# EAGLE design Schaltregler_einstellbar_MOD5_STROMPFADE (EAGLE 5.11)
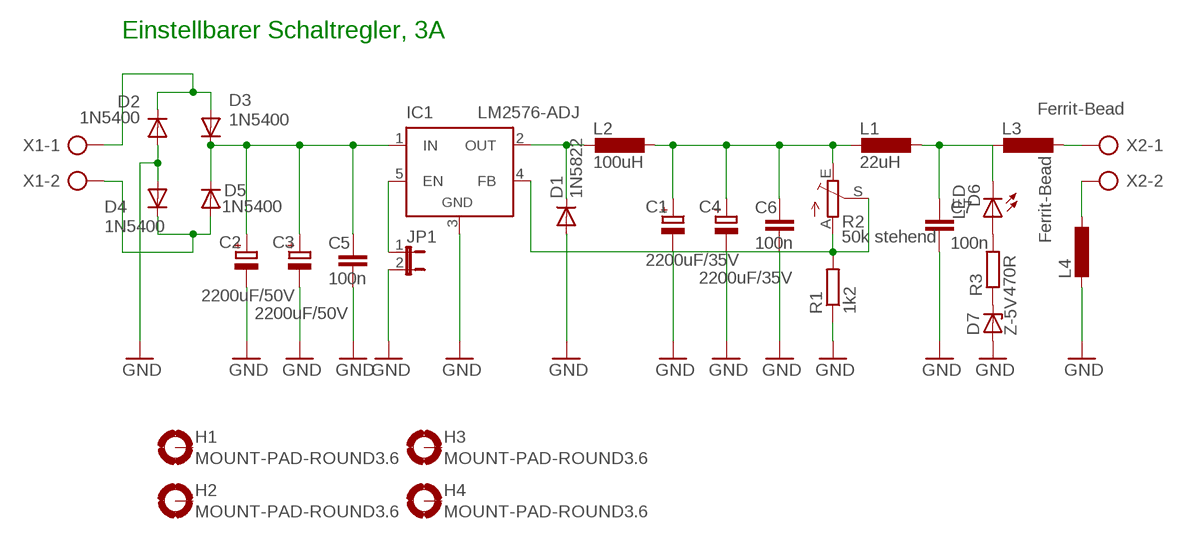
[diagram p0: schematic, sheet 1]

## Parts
C1  2200uF/35V  CPOL-EUE5-13  [E5-13]
C2  2200uF/50V  CPOL-EUE7.5-16  [E7,5-16]
C3  2200uF/50V  CPOL-EUE7.5-16  [E7,5-16]
C4  2200uF/35V  CPOL-EUE5-13  [E5-13]
C5  100n  C-EU025-024X044  [C025-024X044]
C6  100n  C-EU025-024X044  [C025-024X044]
C7  100n  C-EU025-024X044  [C025-024X044]
D1  1N5822  BYW80  [TO220ACS]
D2  1N5400  [DO201-15]
D3  1N5400  [DO201-15]
D4  1N5400  [DO201-15]
D5  1N5400  [DO201-15]
D6  LED  LED5MM  [LED5MM]
D7  Z-5V  ZENER-DIODEF126-10  [F126Z10]
H1  MOUNT-PAD-ROUND3.6  [3,6-PAD]
H2  MOUNT-PAD-ROUND3.6  [3,6-PAD]
H3  MOUNT-PAD-ROUND3.6  [3,6-PAD]
H4  MOUNT-PAD-ROUND3.6  [3,6-PAD]
IC1  LM2576-ADJ  LM2596TH  [TO220-52]
JP1  JP1E  [JP1]
L1  22uH  L-EU2200-12.7  [2200-12.7]
L2  100uH  L-EUTJ5-U1  [TJ5-U1]
L3  Ferrit-Bead  L-EU0207/7  [0207/7]
L4  Ferrit-Bead  L-EU0207/7  [0207/7]
R1  1k2  R-EU_0309/12  [0309/12]
R2  50k stehend  TRIM_EU-PT10S  [PT-10S]
R3  470R  R-EU_0207/7  [0207/7]
X1  AK300/2  [AK300/2]
X2  AK300/2  [AK300/2]

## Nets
GND: C1.- C2.- C3.- C4.- C5.2 C6.2 C7.2 D1.A D2.A D4.A D7.A IC1.3(GND) JP1.2 L4.2 R1.1
N$1: D1.C IC1.2(OUT) L2.2
N$2: IC1.5(EN) JP1.1
N$3: C2.+ C3.+ C5.1 D3.C D5.C IC1.1(IN)
N$4: IC1.4(FB) R1.2 R2.A R2.S
N$5: D2.C D3.A X1.1
N$6: D4.C D5.A X1.2
N$7: L3.1 X2.1
N$9: C7.1 D6.K(C) L1.1 L3.2
N$11: L4.1 X2.2
N$14: C1.+ C4.+ C6.1 L1.2 L2.1 R2.E
N$17: D7.C R3.1
N$18: D6.A R3.2
Unconnected: H1.B3,6(MOUNT) H2.B3,6(MOUNT) H3.B3,6(MOUNT) H4.B3,6(MOUNT)

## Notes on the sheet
- Einstellbarer Schaltregler, 3A

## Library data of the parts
C1-C4 = rcl:CPOL-EU: POLARIZED CAPACITOR, European symbol
C5-C7 = resistor:C-EU: CAPACITOR, European symbol
D1 = diode:BYW80: DIODE
D2-D5 = diode:1N5400: DIODE
D6 = led:LED: LED
D7 = diode:ZENER-DIODE: Z-Diode
H1-H4 = holes:MOUNT-PAD-ROUND: MOUNTING PAD, round
IC1 = linear:LM2596T: STEP-DOWN VOLTAGE REGULATOR
JP1 = jumper:JP1E: JUMPER
L1-L4 = rcl:L-EU: INDUCTOR, European symbol
R1 R3 = rcl:R-EU_: RESISTOR, European symbol
R2 = pot:TRIM_EU-: POTENTIOMETER
X1 X2 = con-ptr500:AK300/2: CONNECTOR

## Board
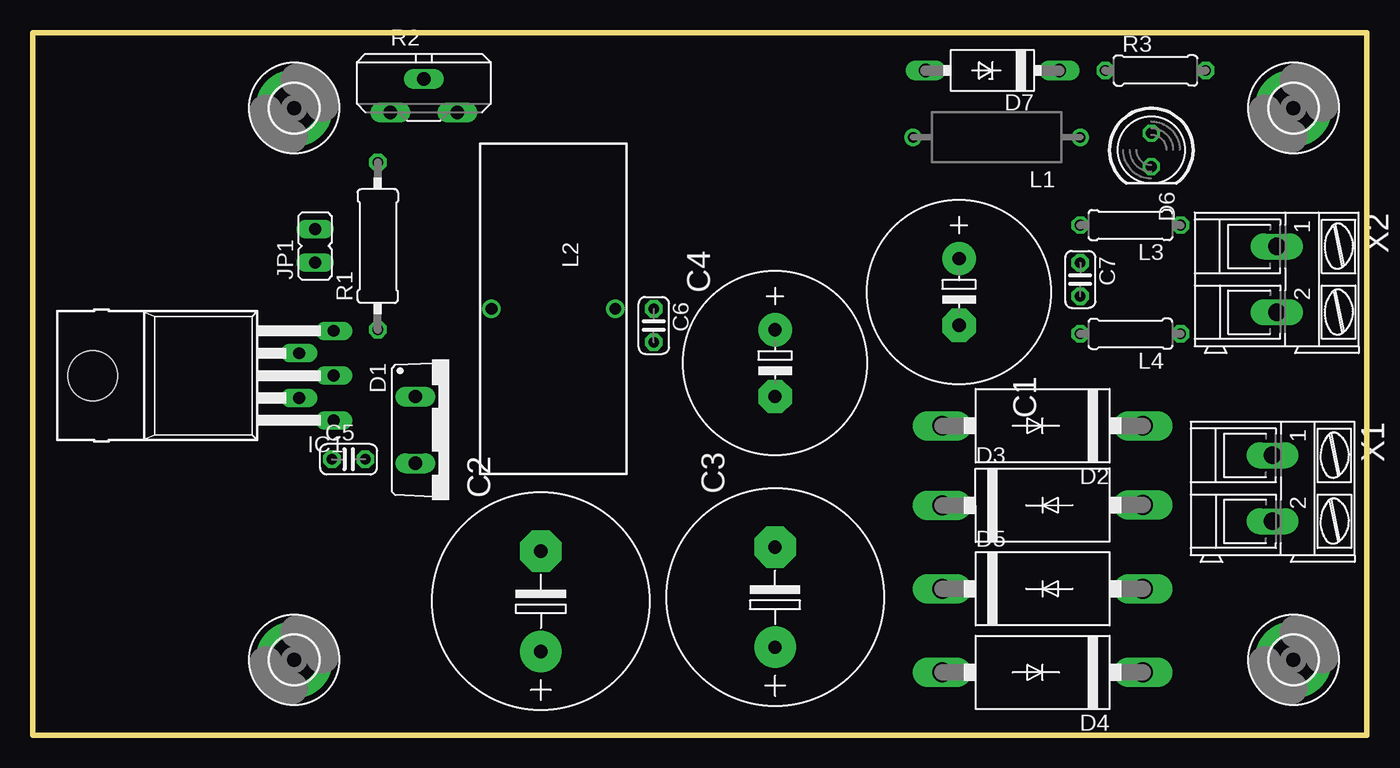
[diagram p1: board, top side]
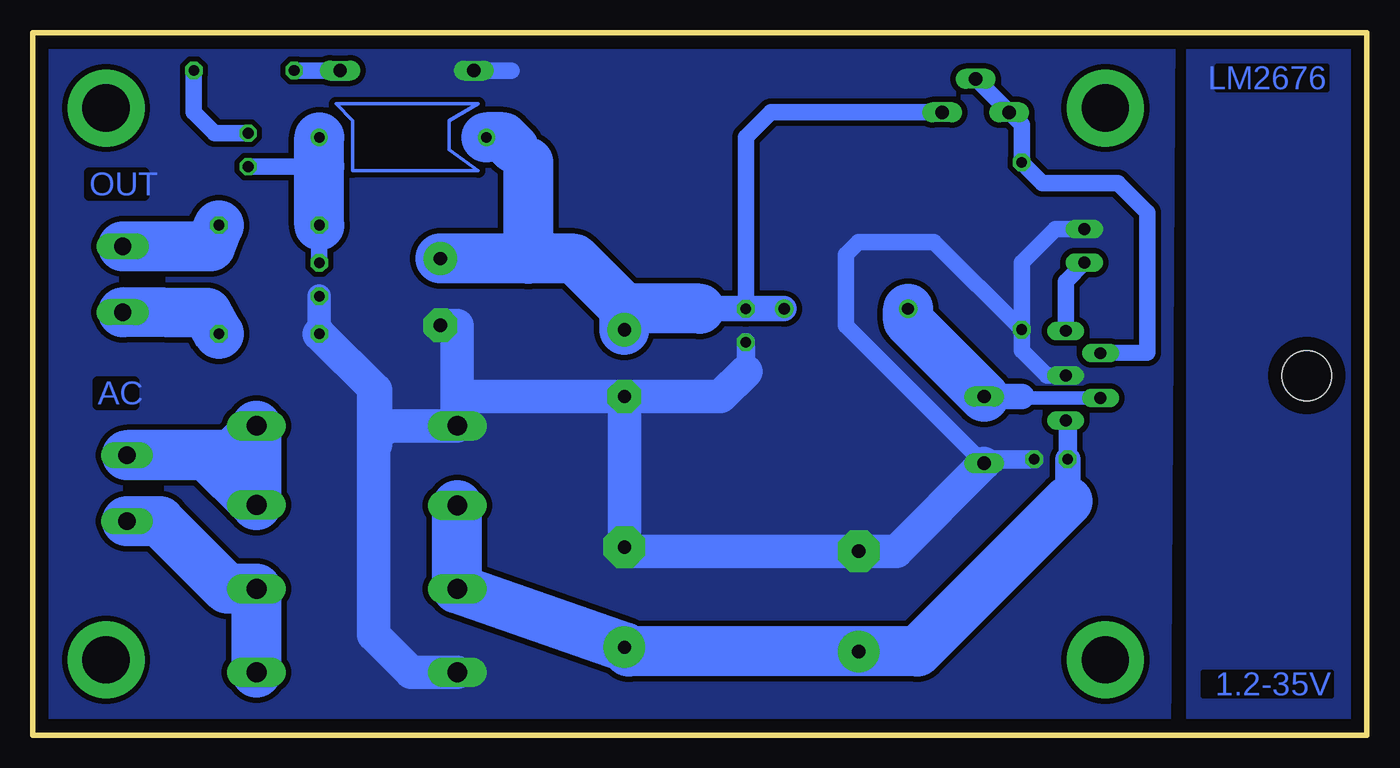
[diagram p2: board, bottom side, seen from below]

Size 101.27 x 53.33 mm. Coordinates in mm from the lower left corner, seen from the top.
Outline: 0,0 101.27,0 101.27,53.33 0,53.33 0,0
Copper layers (1*16): Top 0.035mm / dielectric 1.5mm / Bottom 0.035mm
Design rules "default": minimum track width 10mil, minimum drill 24mil, track to track 8mil, track to pad 8mil, pad to pad 8mil, via to via 8mil, smd to smd 8mil, copper to edge 40mil, drill to drill 8mil, minimum pad ring 10mil, minimum via ring 8mil, stop-mask expansion 4mil, vias tented up to drill 0mil, thermal gap 10mil

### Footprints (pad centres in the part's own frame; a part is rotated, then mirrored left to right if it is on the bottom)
E5-13 = drill 1.016 pad 2.54 round: + -2.54,0 | drill 1.016 pad 2.54 octagon: - 2.54,0
E7,5-16 = drill 1.016 pad 3.15 round: + -3.81,0 | drill 1.016 pad 3.15 octagon: - 3.81,0
C025-024X044 = drill 0.813 octagon: 1 -1.27,0; 2 1.27,0
TO220ACS = drill 1.016 long: A 2.54,-2.54; C -2.54,-2.54
DO201-15 = drill 1.499 long: A 7.62,0; C -7.62,0
LED5MM = drill 0.813 octagon: A -1.27,0; K 1.27,0
F126Z10 = drill 1.016 long: A 5.08,0; C -5.08,0
3,6-PAD = drill 3.6 pad 5.842 round: B3,6 0,0
TO220-52 = drill 0.9 long: 1 -3.4,-21.1; 2 -1.7,-18.47; 3 0,-21.1; 4 1.7,-18.47; 5 3.4,-21.1 | hole 3.8: 0,-2.8
JP1 = drill 0.914 long: 1 0,-1.27; 2 0,1.27
2200-12.7 = drill 0.8 pad 1.27 round: 1 -6.35,0; 2 6.35,0
TJ5-U1 = drill 0.9 round: 1 -4.7,0; 2 4.7,0
0207/7 = drill 0.813 octagon: 1 -3.81,0; 2 3.81,0
0309/12 = drill 0.813 octagon: 1 -6.35,0; 2 6.35,0
PT-10S = drill 1.016 long: A -2.54,-1.27; E 2.54,-1.27; S 0,1.27
AK300/2 = drill 1.321 long: 1 -2.515,0; 2 2.489,0

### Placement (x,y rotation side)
C1  70.32,33.65 270 top
C2  38.57,10.16 90 top
C3  56.35,10.47 90 top
C4  56.35,28.25 270 top
C5  23.96,20.95 0 top
C6  47.14,31.11 270 top
C7  79.53,34.6 270 top
D1  31.58,23.17 270 top
D2  76.67,23.49 180 top
D3  76.67,17.46 0.1 top
D4  76.67,4.76 180 top
D5  76.67,11.11 0 top
D6  84.92,44.45 270 top
D7  72.86,50.48 180 top
H1  95.72,47.62 0 top
H2  19.84,47.62 0 top
H3  95.72,5.71 0 top
H4  19.84,5.71 0 top
IC1  1.74,27.3 90 top
JP1  21.42,37.14 0 top
L1  73.18,45.4 180 top
L2  39.52,32.38 180 top
L3  83.34,38.73 180 top
L4  83.34,30.47 180 top
R1  26.19,37.14 90 top
R2  29.68,48.57 0 top
R3  85.24,50.48 0 top
X1  94.13,18.73 270 top
X2  94.45,34.6 270 top

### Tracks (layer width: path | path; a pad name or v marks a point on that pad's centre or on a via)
GND
  Bottom 1.27: 64.92,50.48 D7.A | JP1.2 23.65,38.41 26.19,35.87 R1.1 | IC1.3 24.28,27.3 26.19,29.2 R1.1 | R1.1 32.85,37.46 38.57,37.46 39.52,36.51 39.52,31.11 D1.A
  Bottom 1.422: D1.A 28.73,20.95 C5.2 | 47.14,27.62 C6.2
  Bottom 1.778: 75.4,25.71 75.24,22.06 73.81,23.49 | L4.2 C7.2
  Bottom 2.54: 69.05,26.03 D2.A 73.81,23.49 | 69.05,26.03 69.05,31.11 C1.- | D4.A 72.54,4.76 75.4,7.62 75.4,25.71 | L4.2 75.24,26.19 75.24,22.06 | C3.- 56.03,13.97 C2.- 35.71,13.97 D1.A | C3.- 56.67,14.28 | C4.- 68.73,25.71 69.05,26.03 | C3.- C4.- | C4.- 49.05,25.71 47.14,27.62
  pour Bottom (isolate 0.406, no thermals): 102.07,53.65 14.76,53.65 15.08,-0.64 102.07,-0.64
N$1
  Bottom 1.016: IC1.2 25.44,25.6 26.19,25.71
  Bottom 1.93: 26.19,25.71 D1.C
  Bottom 3.81: L2.2 34.82,31.49 D1.C
N$2
  Bottom 1.27: IC1.5 22.84,34.43 JP1.1
N$3
  Bottom 0.254: D3.C 67.78,18.41
  Bottom 1.422: C5.1 22.69,23.75 IC1.1
  Bottom 1.93: 22.69,17.77 22.84,18.55 22.69,18.06 C5.1
  Bottom 2.54: D5.C D3.C | 56.03,6.34 C3.+ | 34.12,6.34 C2.+
  Bottom 3.81: C3.+ D5.C | 56.03,6.34 34.12,6.34 22.69,17.77
N$4
  Bottom 1.27: IC1.4 16.66,29.05 16.66,39.68 18.88,41.91 24.6,41.91 R1.2 26.19,46.35 R2.A R2.S
N$5
  Bottom 3.81: D3.A 88.06,21.24 X1.1 94.11,21.27 86.19,21.27 84.29,23.17 | D3.A | D3.A 84.29,23.17 | 84.29,23.17 D2.C
N$6
  Bottom 3.81: D4.C D5.A 86.51,11.11 91.64,16.24 X1.2
N$7
  Bottom 3.81: X2.1 87.81,37.12 L3.1
N$8
  pour Bottom: 13.49,53.65 13.49,-0.64 -0.8,-0.64 -0.8,53.65
N$9
  Bottom 1.27: C7.1 L3.2 | 79.53,43.18 D6.K
  Bottom 3.81: L3.2 79.53,43.18 L1.1
N$11
  Bottom 3.81: X2.2 88.05,32.06 L4.1
N$13
  Bottom 0.254: 76.99,42.86 76.99,46.67 78.26,47.94 67.46,47.94 69.68,46.67 69.68,44.45 67.46,42.86 76.99,42.86
N$14
  Bottom 1.27: R2.E 45.24,47.3 47.14,45.4 C6.1
  Bottom 1.93: 50.64,32.38 C6.1 L2.1
  Bottom 2.54: 63.65,43.49 64.76,44.6
  Bottom 3.81: 63.65,36.18 C1.+ | L1.2 65.56,45.4 64.76,44.6 | 63.65,36.18 63.65,43.49 | 50.64,32.38 56.03,32.38 56.35,32.06 C4.+ 56.35,32.38 60.15,36.18 63.65,36.18
N$16
  Bottom 3.81: 69.05,11.11 69.05,17.46
N$17
  Bottom 1.27: D7.C R3.1
N$18
  Bottom 1.27: R3.2 89.05,47.3 87.46,45.72 D6.A

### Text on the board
Bottom: LM2676 | OUT | AC | 1.2-35V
